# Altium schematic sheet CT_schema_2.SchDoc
size 326 x 327 mm
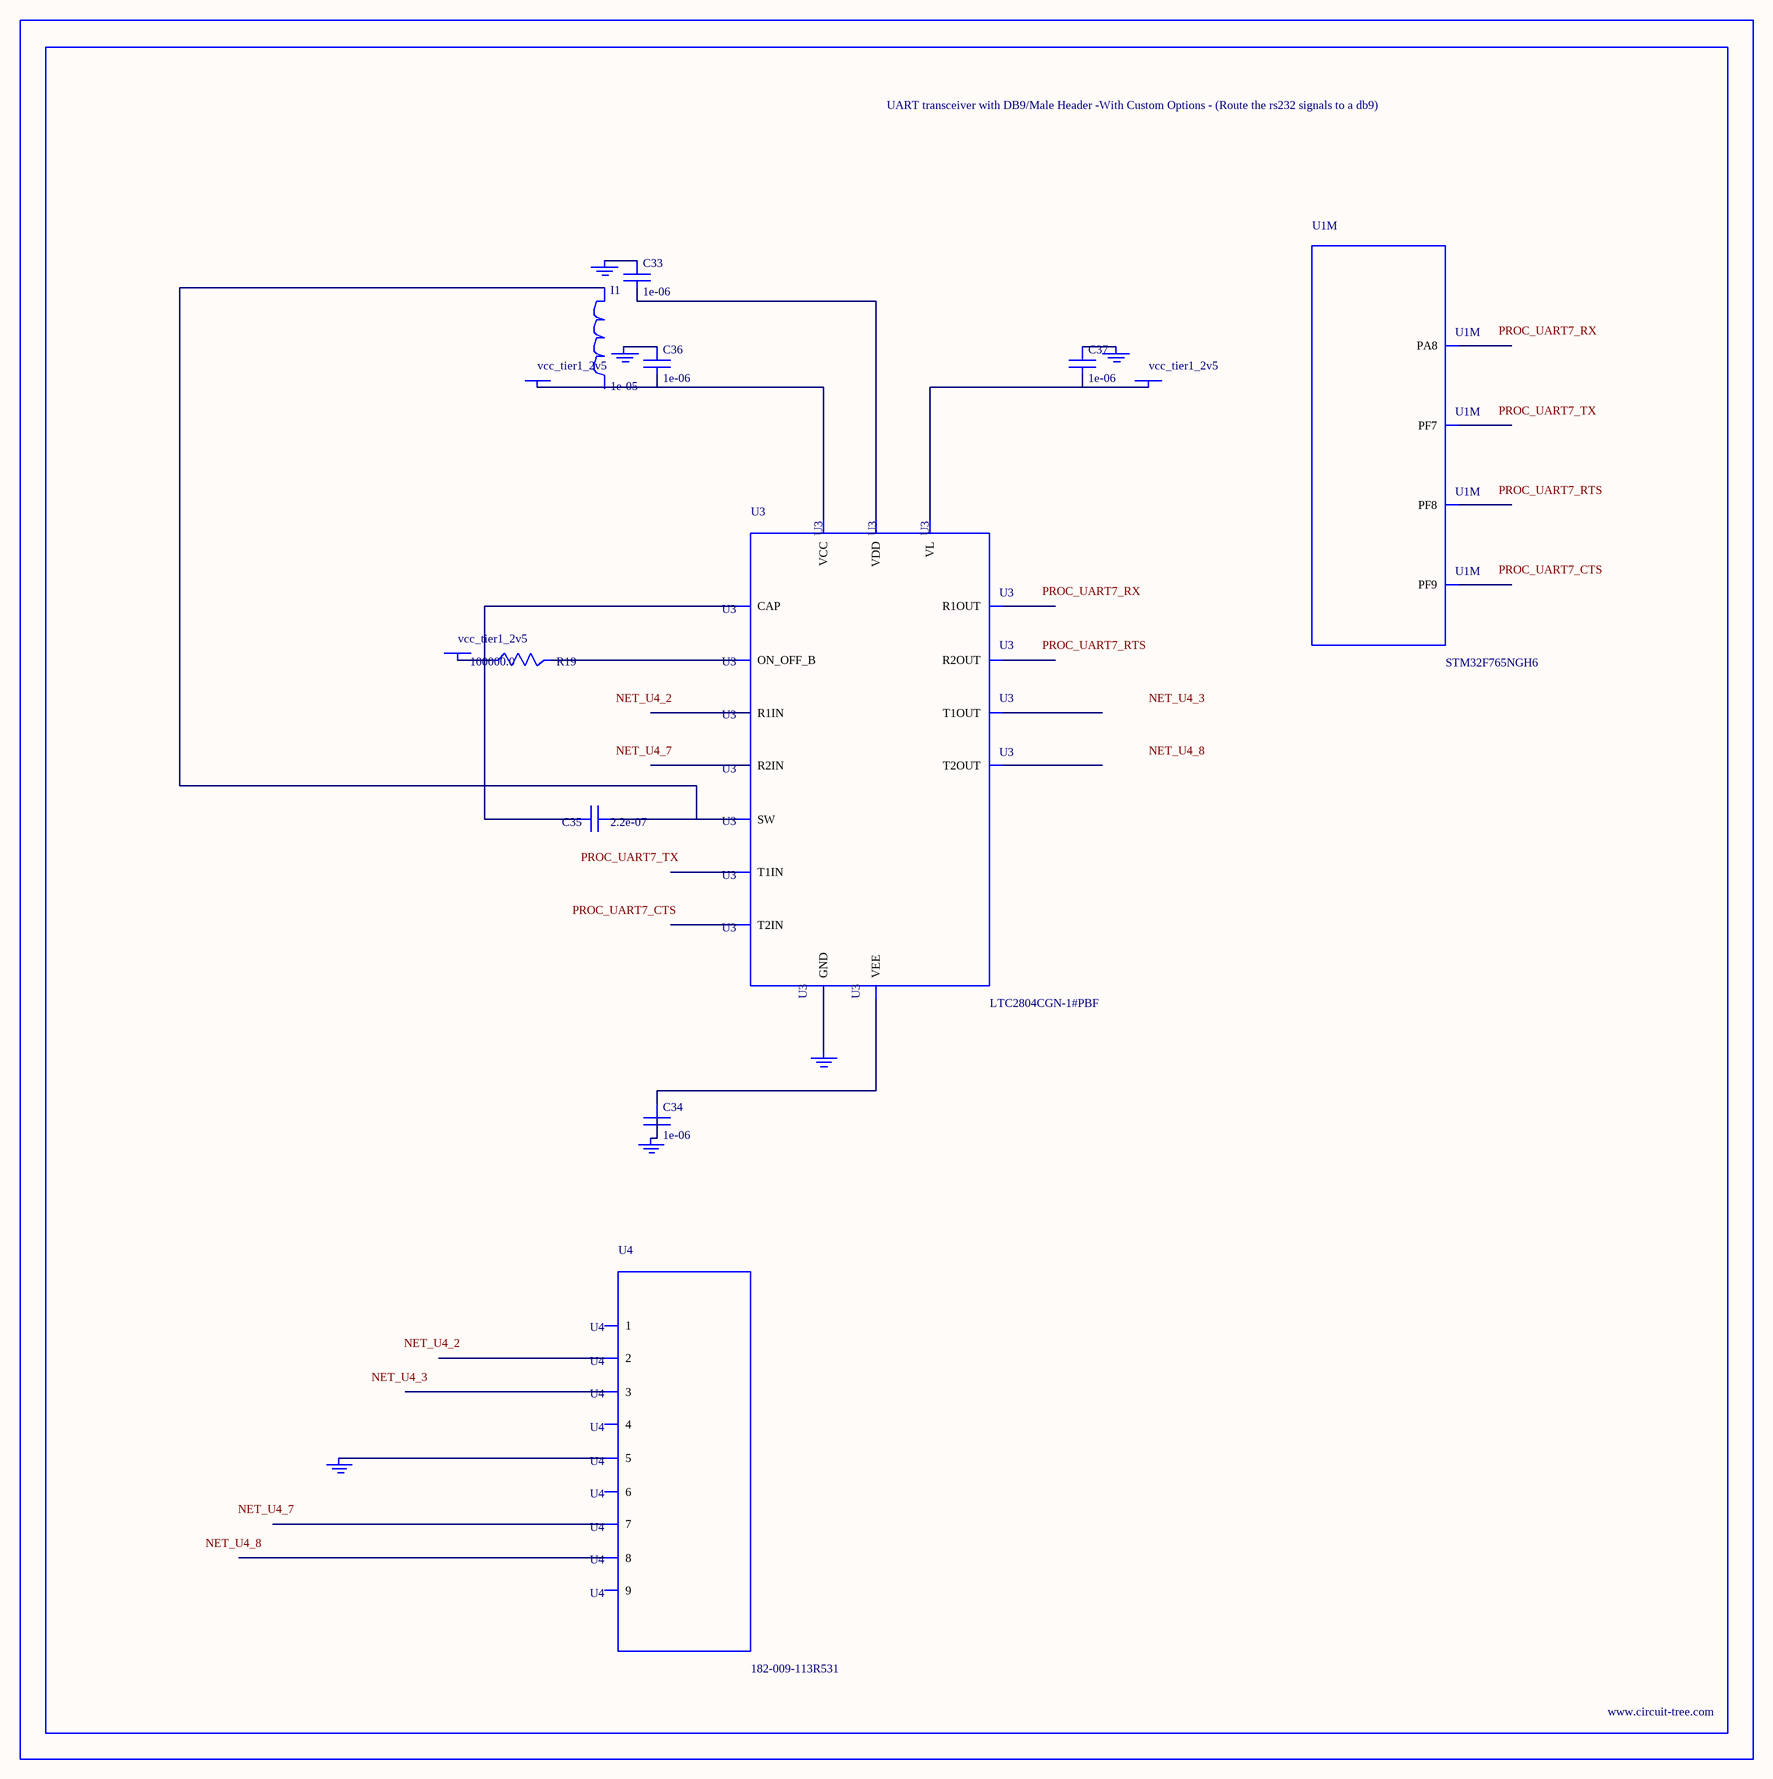
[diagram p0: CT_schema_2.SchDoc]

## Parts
BORDER1  (no value)
C33  1e-06  [C0603]
C34  1e-06  [C0603]
C35  2.2e-07  [C0603]
C36  1e-06  [C0603]
C37  1e-06  [C0603]
GND_INSTANCE_1_0  (no value)
GND_INSTANCE_1_1  (no value)
GND_INSTANCE_1_2  (no value)
GND_INSTANCE_1_3  (no value)
GND_INSTANCE_1_4  (no value)
GND_INSTANCE_1_5  (no value)
I1  1e-05  [L1210]
POWER_INSTANCE_1_0  vcc_tier1_2v5
POWER_INSTANCE_1_1  vcc_tier1_2v5
POWER_INSTANCE_1_2  vcc_tier1_2v5
R19  100000.0  [R0603]
U1  STM32F765NGH6  [TFBGA216]  (part M of 18)
U3  LTC2804CGN-1#PBF  [SSOP-16]
U4  182-009-113R531  [182-009-MALE]

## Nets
NetC33_1: C33.1 GND_INSTANCE_1_1.0(GND)
NetC33_2: C33.2 U3.6(VDD)
NetC34_1: C34.1 U3.9(VEE)
NetC34_2: C34.2 GND_INSTANCE_1_2.0(GND)
NetC35_1: C35.1 I1.1 U3.7(SW)
NetC35_2: C35.2 U3.10(CAP)
NetC36_1: C36.1 GND_INSTANCE_1_0.0(GND)
NetC36_2: C36.2 POWER_INSTANCE_1_0.0(PWR) U3.5(VCC)
NetC37_1: C37.1 GND_INSTANCE_1_3.0(GND)
NetC37_2: C37.2 POWER_INSTANCE_1_2.0(PWR) U3.12(VL)
NetGND_INSTANCE_1_4_0: GND_INSTANCE_1_4.0(GND) U3.8(GND)
NetGND_INSTANCE_1_5_0: GND_INSTANCE_1_5.0(GND) U4.5
NetPOWER_INSTANCE_1_1_0: POWER_INSTANCE_1_1.0(PWR) R19.1
NetR19_2: R19.2 U3.11(ON_OFF_B)

Not connected (* = marked no-connect by the designer): I1 2; U1 F15(PA8) K1(PF7) L2(PF9) L3(PF8); U3 1(R1IN) 2(R2IN) 3(T1OUT) 4(T2OUT) 13(T2IN) 14(T1IN) 15(R2OUT) 16(R1OUT); U4 1 2 3 4 6 7 8 9

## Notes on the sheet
- Labels drawn without touching a wire or pin: NET_U4_2, NET_U4_3, NET_U4_7, NET_U4_8, PROC_UART7_CTS, PROC_UART7_RTS, PROC_UART7_RX, PROC_UART7_TX

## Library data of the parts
BORDER1 = BORDER_PAGE1
C33 C34 C36 C37 = C0603C105K3RACTU
C35 = C0603C224K3RAC
GND_INSTANCE_1_0-GND_INSTANCE_1_5 = GND
I1 = CBC3225T100MR
POWER_INSTANCE_1_0-POWER_INSTANCE_1_2 = PWR
R19 = RC0603JR-07100KL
